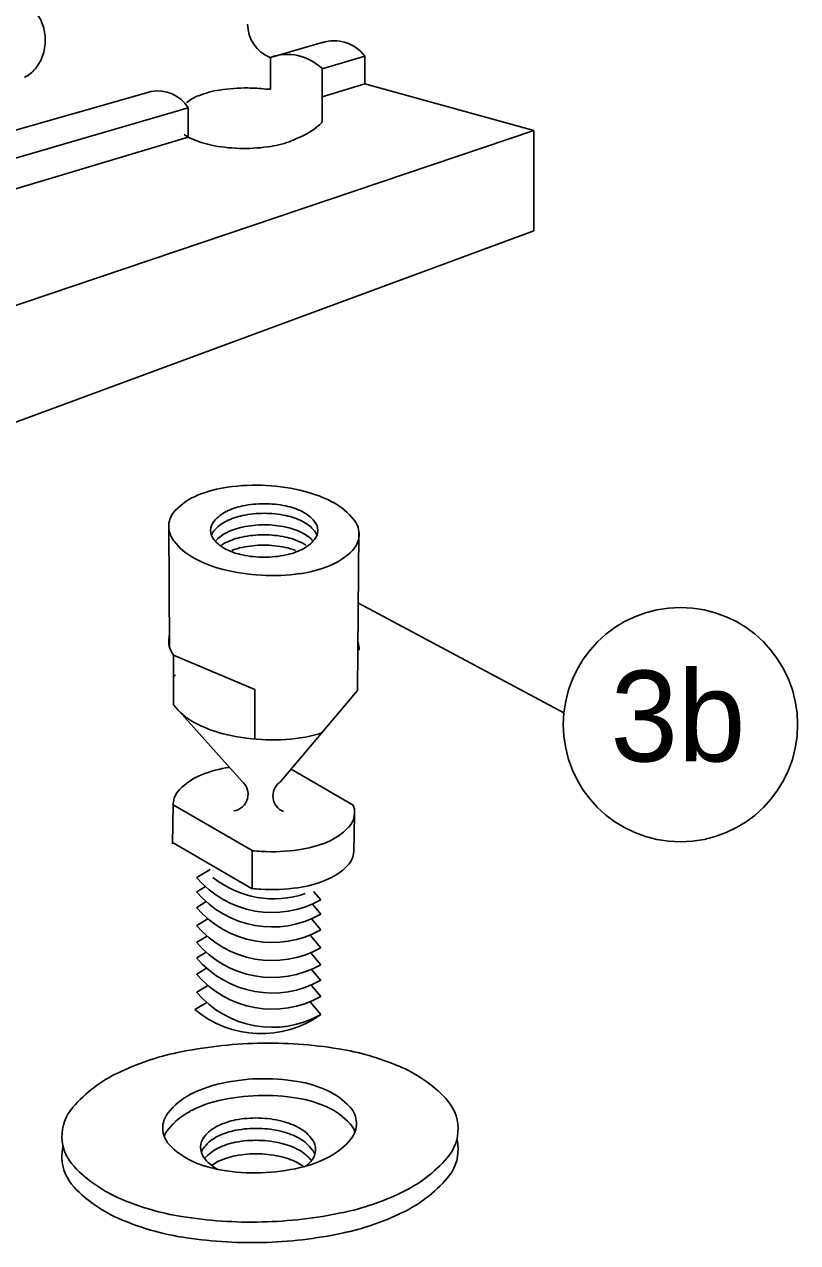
# Model space of a CAD drawing. Extents: x 12.3 to 19.6, y 5.8 to 16.1.
# Drawn here: x 14.807 to 15.538, y 7.686 to 8.839 of the extents above; entities that cross this region are included whole.
import ezdxf

# ---------------------------------------------------------------- set-up
doc = ezdxf.new("R2010")
doc.units = 0
doc.layers.add('DETL-LINE', color=7, linetype='Continuous')
doc.layers.add('DETL-NOTE', color=7, linetype='Continuous')

msp = doc.modelspace()

# ---------------------------------------------------------------- linework, layer by layer
at = {"layer": 'DETL-LINE'}
for p, q in [((15.0393, 8.8077), (15.0905, 8.8223)), ((15.0393, 8.8077), (15.0393, 8.7777)), ((15.0882, 8.797), (15.1286, 8.8088)), ((15.1286, 8.7827), (15.1286, 8.8088)), ((15.0882, 8.7465), (15.0882, 8.797)), ((15.0882, 8.7705), (15.1286, 8.7827)), ((15.2885, 8.7384), (15.1286, 8.7827)), ((14.7035, 8.7119), (14.9265, 8.7755)), ((14.7035, 8.6849), (14.9615, 8.7601)), ((14.9615, 8.7324), (14.9615, 8.7601)), ((14.6331, 8.5174), (15.2885, 8.7384)), ((15.2885, 8.6437), (15.2885, 8.7384)), ((14.692, 8.6513), (14.9615, 8.7324)), ((14.6331, 8.4014), (15.2885, 8.6437)), ((14.9432, 8.365), (14.944, 8.2495)), ((15.1231, 8.3583), (15.1218, 8.2087)), ((14.9478, 8.1953), (14.9478, 8.2422)), ((15.0245, 8.2097), (14.9478, 8.2421)), ((15.0245, 8.2097), (15.0245, 8.1628)), ((15.1218, 8.2087), (15.0481, 8.1217)), ((14.9478, 8.1953), (15.0123, 8.1229)), ((15.1177, 8.1003), (15.0589, 8.1345)), ((14.9475, 8.1007), (14.9468, 8.0637)), ((15.0222, 8.0573), (14.9475, 8.1007)), ((15.0516, 8.0942), (15.0516, 8.0942)), ((15.1188, 8.0914), (15.1181, 8.0555)), ((15.0222, 8.0213), (14.9475, 8.0647)), ((15.0222, 8.0213), (15.0222, 8.0573)), ((14.9696, 8.032), (14.9824, 8.0396)), ((14.9696, 8.0184), (14.9779, 8.0233)), ((15.0802, 8.0188), (15.087, 8.0107)), ((14.9696, 8.0036), (14.9786, 8.0091)), ((15.079, 8.0067), (15.087, 7.9972)), ((14.9696, 7.9865), (14.9802, 7.9929)), ((15.0783, 7.9928), (15.087, 7.9824)), ((14.9696, 7.9706), (14.9794, 7.9765)), ((15.0768, 7.9774), (15.087, 7.9653)), ((14.9696, 7.9559), (14.9786, 7.9613)), ((15.0775, 7.9606), (15.087, 7.9494)), ((14.9696, 7.9405), (14.979, 7.9462)), ((15.0783, 7.945), (15.087, 7.9346)), ((14.9696, 7.9234), (14.9802, 7.9298)), ((15.0779, 7.9301), (15.087, 7.9193)), ((14.9678, 7.9069), (14.9791, 7.9137)), ((15.0768, 7.9143), (15.087, 7.9022))]:
    msp.add_line(p, q, dxfattribs=at)
for centre, radius, start, end in [((14.7873, 8.8265), 0.0386, 18.7719, 39.3704), ((14.78, 8.824), 0.0464, 0, 18.7719), ((15.0517, 8.8392), 0.0339, 180, 248.4327), ((14.78, 8.824), 0.0464, 341.2281, 360), ((15.0994, 8.7868), 0.0366, 37.0423, 107.8464), ((14.7873, 8.8215), 0.0386, 320.6296, 341.2281), ((15.0552, 8.7633), 0.0472, 45.6707, 109.7184), ((14.792, 8.8177), 0.0325, 296.7848, 320.6296), ((14.9324, 8.7416), 0.0345, 32.5345, 99.8594), ((14.9892, 8.7266), 0.0483, 111.447, 126.986), ((15.0058, 8.6842), 0.0938, 98.9315, 111.447), ((15.0164, 8.6168), 0.162, 89.4168, 98.9315), ((15.0164, 8.6168), 0.162, 83.4776, 89.4168), ((15.0354, 8.7193), 0.0585, 86.1601, 90.5057), ((15.0449, 8.7877), 0.0598, 289.3747, 316.3788), ((14.9852, 8.7745), 0.0483, 235.5747, 247.3866), ((15.0027, 8.8165), 0.0938, 247.3866, 259.902), ((15.0253, 8.8162), 0.0938, 278.9315, 291.447), ((15.0419, 8.7739), 0.0483, 291.447, 298.1604), ((15.0147, 8.8836), 0.162, 259.902, 269.4168), ((15.0147, 8.8836), 0.162, 269.4168, 278.9315), ((15.0251, 8.2128), 0.1902, 86.8798, 97.9507), ((15.0251, 8.2128), 0.1902, 75.8089, 86.8798), ((14.9956, 8.3338), 0.0648, 112.1647, 135.6331), ((15.0148, 8.2867), 0.1156, 97.9507, 112.1647), ((15.0434, 8.2851), 0.1156, 61.5949, 75.8089), ((14.9648, 8.364), 0.0216, 135.6331, 176.8798), ((15.0257, 8.322), 0.0627, 101.7009, 116.5651), ((15.0334, 8.2845), 0.101, 90, 101.7009), ((15.0334, 8.2845), 0.101, 78.2991, 90), ((15.0412, 8.322), 0.0627, 63.4349, 78.2991), ((15.0676, 8.3299), 0.0648, 38.1265, 61.5949), ((14.9962, 8.3602), 0.0135, 140.3607, 180), ((15.0139, 8.3456), 0.0364, 116.5651, 140.3607), ((15.0139, 8.3365), 0.0364, 116.5651, 140.3607), ((15.0257, 8.3129), 0.0627, 101.7009, 116.5651), ((15.0334, 8.2754), 0.101, 90, 101.7009), ((15.0334, 8.2754), 0.101, 78.2991, 90), ((15.0412, 8.3129), 0.0627, 63.4349, 78.2991), ((15.053, 8.3456), 0.0364, 39.6393, 63.4349), ((15.053, 8.3365), 0.0364, 39.6393, 63.4349), ((15.0707, 8.3602), 0.0135, 0, 39.6393), ((15.1016, 8.3565), 0.0216, 356.8798, 38.1265), ((14.9648, 8.364), 0.0216, 176.8798, 218.1265), ((14.9962, 8.3602), 0.0135, 180, 219.6393), ((14.9962, 8.3511), 0.0135, 140.3607, 160.1846), ((15.0139, 8.3255), 0.0364, 116.5651, 137.3265), ((15.0257, 8.302), 0.0627, 101.7009, 116.5651), ((15.033, 8.2551), 0.101, 90, 101.7009), ((15.0334, 8.2645), 0.101, 90, 101.7009), ((15.033, 8.2551), 0.101, 78.2991, 90), ((15.0334, 8.2645), 0.101, 78.2991, 90), ((15.0412, 8.302), 0.0627, 63.4349, 78.2991), ((15.053, 8.3255), 0.0364, 42.6735, 63.4349), ((15.0707, 8.3602), 0.0135, 320.3607, 360), ((15.0707, 8.3511), 0.0135, 19.8154, 39.6393), ((14.9987, 8.3906), 0.0648, 218.1265, 241.5949), ((15.0139, 8.3749), 0.0364, 219.6393, 243.4349), ((15.0134, 8.3161), 0.0364, 116.5651, 124.0835), ((15.0252, 8.2926), 0.0627, 101.7009, 116.5651), ((15.0252, 8.2828), 0.0627, 101.7009, 111.0033), ((15.033, 8.2453), 0.101, 90, 101.7009), ((15.033, 8.2453), 0.101, 78.2991, 90), ((15.0407, 8.2926), 0.0627, 63.4349, 78.2991), ((15.0407, 8.2828), 0.0627, 68.9967, 78.2991), ((15.0525, 8.3161), 0.0364, 55.9165, 63.4349), ((15.053, 8.3749), 0.0364, 296.5651, 320.3607), ((15.1016, 8.3565), 0.0216, 315.6331, 356.8798), ((15.0229, 8.4354), 0.1156, 241.5949, 255.8089), ((15.0257, 8.3984), 0.0627, 243.4349, 258.2991), ((15.0334, 8.4359), 0.101, 258.2991, 270), ((15.0334, 8.4359), 0.101, 270, 281.7009), ((15.0412, 8.3984), 0.0627, 281.7009, 296.5651), ((15.0707, 8.3867), 0.0648, 292.1647, 315.6331), ((15.0412, 8.5077), 0.1902, 255.8089, 266.8798), ((15.0515, 8.4338), 0.1156, 277.9507, 292.1647), ((15.0412, 8.5077), 0.1902, 266.8798, 277.9507), ((14.9648, 8.2555), 0.0216, 164.6831, 176.8798), ((14.9648, 8.2555), 0.0216, 176.8798, 218.1265), ((15.1016, 8.248), 0.0216, 356.8798, 17.3595), ((14.9648, 8.2086), 0.0216, 135.6331, 141.9986), ((14.9987, 8.2352), 0.0648, 218.1265, 241.5949), ((14.9648, 8.2086), 0.0216, 218.0014, 218.1265), ((15.0229, 8.28), 0.1156, 241.5949, 255.8089), ((15.0412, 8.3523), 0.1902, 255.8089, 266.8798), ((15.0412, 8.3523), 0.1902, 266.8798, 277.9507), ((15.0515, 8.2784), 0.1156, 277.9507, 288.3001), ((14.9974, 8.0719), 0.0617, 112.1647, 135.6331), ((15.0157, 8.027), 0.1101, 97.9507, 112.1647), ((15.0255, 7.9567), 0.1811, 97.9092, 97.9507), ((14.968, 8.1006), 0.0206, 135.6331, 176.8798), ((15.0023, 8.1106), 0.0159, 278.8392, 50.8345), ((15.0577, 8.109), 0.016, 126.9935, 247.5653), ((14.968, 8.1006), 0.0206, 176.8798, 179.8427), ((15.0983, 8.0935), 0.0206, 315.6331, 356.8798), ((15.0983, 8.0935), 0.0206, 356.8798, 19.4006), ((15.0689, 8.1222), 0.0617, 292.1647, 315.6331), ((15.0408, 8.2374), 0.1811, 264.0811, 266.8798), ((15.0408, 8.2374), 0.1811, 266.8798, 277.9507), ((15.0507, 8.1671), 0.1101, 277.9507, 292.1647), ((15.0976, 8.0576), 0.0206, 315.6331, 356.8798), ((15.0976, 8.0576), 0.0206, 356.8798, 3.7998), ((15.0682, 8.0864), 0.0617, 292.1647, 315.6331), ((15.0411, 8.0922), 0.0935, 220.0991, 299.4052), ((15.0426, 8.1037), 0.092, 231.2376, 288.847), ((15.0401, 8.2016), 0.1811, 264.3037, 266.8798), ((15.0401, 8.2016), 0.1811, 266.8798, 277.9507), ((15.05, 8.1312), 0.1101, 277.9507, 292.1647), ((15.0411, 8.0786), 0.0935, 220.0991, 299.4052), ((15.0411, 8.0639), 0.0935, 220.0991, 299.4052), ((15.0411, 8.0468), 0.0935, 220.0991, 299.4052), ((15.0411, 8.0308), 0.0935, 220.0991, 299.4052), ((15.0411, 8.0161), 0.0935, 220.0991, 299.4052), ((15.0411, 8.0008), 0.0935, 220.0991, 299.4052), ((15.0411, 7.9837), 0.0935, 220.0991, 299.4052), ((15.0305, 7.9815), 0.0974, 229.9667, 305.5002), ((15.0373, 7.4614), 0.4138, 91.3631, 101.9583), ((15.0373, 7.4614), 0.4138, 80.7679, 91.3631), ((15.0029, 7.624), 0.2477, 101.9583, 115.6669), ((15.064, 7.6254), 0.2477, 67.0592, 80.7679), ((15.1078, 7.7291), 0.1352, 43.8907, 67.0592), ((14.9541, 7.7254), 0.1352, 115.6669, 138.8355), ((15.0336, 7.6532), 0.1884, 91.7888, 103.1512), ((15.0336, 7.6532), 0.1884, 80.4264, 91.7888), ((15.0457, 7.7249), 0.1157, 65.9087, 80.4264), ((14.9939, 7.7682), 0.0658, 117.6689, 141.2983), ((15.017, 7.724), 0.1157, 103.1512, 117.6689), ((15.0336, 7.6374), 0.1884, 91.7888, 103.1512), ((15.0336, 7.6374), 0.1884, 80.4264, 91.7888), ((15.066, 7.7704), 0.0658, 42.2793, 65.9087), ((14.8836, 7.7871), 0.0414, 138.8355, 181.3631), ((15.017, 7.7083), 0.1157, 103.1512, 117.6689), ((15.0457, 7.7092), 0.1157, 65.9087, 80.4264), ((15.066, 7.7547), 0.0658, 42.2793, 65.9087), ((15.0977, 7.7992), 0.023, 1.7888, 42.2793), ((15.1754, 7.794), 0.0414, 1.3631, 43.8907), ((14.9605, 7.7949), 0.023, 141.2983, 181.7888), ((14.9939, 7.7524), 0.0658, 117.6689, 141.2983), ((15.0187, 7.7385), 0.0652, 100.8472, 116.3613), ((15.0257, 7.7018), 0.1026, 88.4935, 100.8472), ((15.0257, 7.7018), 0.1026, 76.1398, 88.4935), ((14.9605, 7.7949), 0.023, 181.7888, 222.2793), ((14.9605, 7.7792), 0.023, 141.2983, 160.0349), ((15.0071, 7.7618), 0.0392, 116.3613, 140.4192), ((15.0187, 7.7287), 0.0652, 100.8472, 116.3613), ((15.0257, 7.692), 0.1026, 88.4935, 100.8472), ((15.0257, 7.692), 0.1026, 76.1398, 88.4935), ((15.0347, 7.7381), 0.0652, 60.6257, 76.1398), ((15.0347, 7.7283), 0.0652, 60.6257, 76.1398), ((15.0474, 7.7608), 0.0392, 36.5678, 60.6257), ((15.0977, 7.7835), 0.023, 19.9651, 42.2793), ((15.0977, 7.7992), 0.023, 321.2983, 1.7888), ((15.1754, 7.794), 0.0414, 318.8355, 1.3631), ((14.8836, 7.7871), 0.0414, 181.3631, 223.8907), ((14.9922, 7.8237), 0.0658, 222.2793, 245.9087), ((14.9893, 7.7766), 0.016, 140.4192, 178.4935), ((15.0071, 7.752), 0.0392, 116.3613, 140.4192), ((15.0187, 7.7174), 0.0652, 100.8472, 116.3613), ((15.0257, 7.6807), 0.1026, 88.4935, 100.8472), ((15.0257, 7.6807), 0.1026, 76.1398, 88.4935), ((15.0347, 7.717), 0.0652, 60.6257, 76.1398), ((15.0474, 7.751), 0.0392, 36.5678, 60.6257), ((15.0661, 7.7746), 0.016, 358.4935, 36.5678), ((15.0643, 7.826), 0.0658, 297.6689, 321.2983), ((15.1754, 7.7747), 0.0414, 1.3631, 13.5108), ((14.8836, 7.7677), 0.0414, 166.4892, 181.3631), ((14.9893, 7.7766), 0.016, 178.4935, 216.5678), ((14.9893, 7.7668), 0.016, 140.4192, 162.1518), ((15.0071, 7.7407), 0.0392, 116.3613, 139.795), ((15.0187, 7.7047), 0.0652, 100.8472, 116.3613), ((15.0257, 7.6679), 0.1026, 88.4935, 100.8472), ((15.0257, 7.6679), 0.1026, 76.1398, 88.4935), ((15.0474, 7.7397), 0.0392, 38.4706, 60.6257), ((15.0412, 7.8701), 0.1157, 283.1512, 297.6689), ((15.0661, 7.7746), 0.016, 320.4192, 358.4935), ((15.0661, 7.7648), 0.016, 17.8482, 36.5678), ((15.1754, 7.7747), 0.0414, 318.8355, 1.3631), ((14.8836, 7.7677), 0.0414, 181.3631, 223.8907), ((14.9511, 7.8521), 0.1352, 223.8907, 247.0592), ((15.0125, 7.8692), 0.1157, 245.9087, 260.4264), ((15.0079, 7.7904), 0.0392, 216.5678, 240.6257), ((15.0071, 7.728), 0.0392, 116.3613, 126.5096), ((15.0207, 7.8131), 0.0652, 240.6257, 241.3679), ((15.0246, 7.9409), 0.1884, 271.7888, 283.1512), ((15.0347, 7.7043), 0.0652, 60.6257, 76.1398), ((15.0474, 7.7269), 0.0392, 53.2089, 60.6257), ((15.0482, 7.7894), 0.0392, 308.816, 320.4192), ((15.1048, 7.8557), 0.1352, 295.6669, 318.8355), ((15.0246, 7.9409), 0.1884, 260.4264, 271.7888), ((15.1048, 7.8364), 0.1352, 295.6669, 318.8355), ((14.9511, 7.8327), 0.1352, 223.8907, 247.0592), ((15.0561, 7.9571), 0.2477, 281.9583, 295.6669), ((14.995, 7.9557), 0.2477, 247.0592, 260.7679), ((15.0216, 8.1197), 0.4138, 260.7679, 271.3631), ((15.0216, 8.1197), 0.4138, 271.3631, 281.9583), ((15.0561, 7.9378), 0.2477, 281.9583, 295.6669), ((14.995, 7.9363), 0.2477, 247.0592, 260.7679), ((15.0216, 8.1003), 0.4138, 260.7679, 271.3631), ((15.0216, 8.1003), 0.4138, 271.3631, 281.9583)]:
    msp.add_arc(centre, radius, start, end, dxfattribs=at)
at = {"layer": 'DETL-NOTE'}
msp.add_line((15.1225, 8.2915), (15.3169, 8.1877), dxfattribs=at)
msp.add_circle((15.4271, 8.1765), 0.1108, dxfattribs=at)

# ---------------------------------------------------------------- texts
msp.add_text('3b', height=0.0858, dxfattribs=at).set_placement((15.3609, 8.1417))

doc.saveas('drawing.dxf')
